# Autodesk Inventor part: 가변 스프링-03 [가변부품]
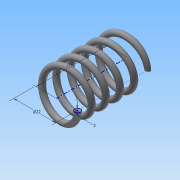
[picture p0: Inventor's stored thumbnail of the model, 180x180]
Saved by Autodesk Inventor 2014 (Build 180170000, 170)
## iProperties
Created: 2015-09
Part Number: 가변 스프링-03 [가변부품]
Material: 강철, 탄소
Document SubType Name: Modeling
Designer: study
Density: 7.87 g/cm^3
Appearance: 반연마
Mass: 18.8111 g
Surface Area: 32.4633 cm^2
Volume: 2.39023 cm^3
Author: study
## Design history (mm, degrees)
sketch "스케치1"
  geometry: L1 (0, 0)-(11, 0); L2 (11, 0)-(11, 28.893); L3 (11, 28.893)-(0, 28.893); L4 (0, 28.893)-(0, 0); C1 r 1.5 at (11, 0)
  constraints: 8 end point, 2 parallel, 1 centre point, 1 coincident, 1 horizontal, 1 perpendicular
  dimensions: "d0" = 28.89259 distance of L3.end L1.start (derived); "d1" = 22 diameter of L2 L4; "d2" = 3 diameter of C1
feature "코일1" sketch "스케치1" pitch "d3" = 10; turns "d5" = 5; dims "d4" = 28.89259 (= d0), "d6" = 0, angle "d7" = 90 deg, angle "d8" = 90 deg, "d9" = 0, "d10" = 0
sketch "스케치2"
  geometry: L1 (-12.5, 0)-(-9.5, 0) reference; 1 further point
  constraints: 1 horizontal alignment
extrude "돌출1" cut sketch "스케치2" distance "d11" = 10; taper "d12" = 0 deg
node "작업 평면1"
sketch "스케치3"
  geometry: L1 (-9.5, 0)-(-12.5, 0) reference; 1 further point
  constraints: 1 horizontal alignment
extrude "돌출2" cut sketch "스케치3" distance "d14" = 10; taper "d15" = 0 deg
node "솔리드1"
node "절단 모서리 투영1"
node "절단 모서리 투영2"
other parameters: "d13" = 28.89259 (= d0)
